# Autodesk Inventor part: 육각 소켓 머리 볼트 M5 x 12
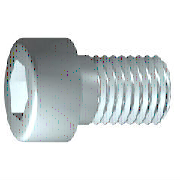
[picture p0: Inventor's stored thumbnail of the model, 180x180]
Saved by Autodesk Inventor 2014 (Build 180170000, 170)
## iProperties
Created: 2012-02
Part Number: 육각 소켓 머리 볼트 M5 x 12
Material: 강철, 연강
Description: 6각 소켓 머리 캡 나사
Document SubType Name: Modeling
Standard: ISO 4762
Designer: mdu-01
Standard Revision: Fourth edition 2004-03-01
Standards Organization: ISO
Language: ko-KR
Size Designation: M5 x 12
Categories: <MemberInstance><Categories><Category DisplayName="조임쇠" InternalName="e4da775c-781d-43d5-af7c-5136215cf5a6" Mnemonic="FSTN"><Category DisplayName="볼트" InternalN
Density: 7.86 g/cm^3
Appearance: 강철
Mass: 3.72825 g
Surface Area: 4.62573 cm^2
Volume: 0.474332 cm^3
Author: mdu-01
IsCustomPart: 1
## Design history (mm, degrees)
sketch "스케치1"
  geometry: L1 (-1.167, 0)-(12, 0); L2 (12, 0)-(12, 2.5); L3 (12, 2.5)-(2, 2.5); L4 (2, 2.5)-(1.509, 2.5); L5 (1.509, 2.5)-(0, 2.5); L6 (0, 2.5)-(0, 4.25); L7 (0, 4.25)-(-5, 4.25); L8 (-5, 4.25)-(-5, 2.309); L9 (-5, 2.309)-(-2.5, 2.309); L10 (-2.5, 2.309)-(-1.167, 0); L11 (-8.4, 0)-(15.4, 0) reference; L12 (0, -0.85)-(0, 5.1) reference; L13 (2, 2.5)-(0, 2.5)
  constraints: 22 end point, 6 parallel, 2 collinear, 2 perpendicular, 1 horizontal, 1 point on line
  dimensions: "d1" = 10 distance from line of L3.end L2 (= GEL); "d2" = 0.49086 distance of L4.end L3.end (computed from GAL); "d3" = 5 distance between parallel lines of L8 L6 (= KOH); "d4" = 2.5 distance of L8.end L9.end (= INTI); "d5" = 60 deg angle of L10 L1; "d6" = 5 diameter of L3 L1 (= GD); "d7" = 5 diameter of L5 L1 (= BDM); "d8" = 4.6188 diameter of L9 L1 (= 1.1547 x SW); "d9" = 8.5 diameter of L7 L1 (= KOD); "d26" = 12 distance between parallel lines of L12 L2 (= NLG)
revolve "본체" sketch "스케치1" stored, may be unused: angle "d10" = 90 deg
sketch "스케치2"
  geometry: L1 (0, -5.95)-(0, 5.95) reference; L2 (-5.95, 0)-(5.95, 0) reference; L3 (2.309, 0)-(1.155, -2); L4 (1.155, -2)-(-1.155, -2); L5 (-1.155, -2)-(-2.309, 0); L6 (-2.309, 0)-(-1.155, 2); L7 (-1.155, 2)-(1.155, 2); L8 (1.155, 2)-(2.309, 0); 2 further points
  constraints: 12 end point, 1 coincident, 1 horizontal alignment, 1 point on line, 12 other
extrude "슬롯" join sketch "스케치2" stored distance "d11" = 10; taper "d12" = 0 deg
workplane "Work Plane1"
fillet "Fillet2" dims "d30" = 0.1 (= R)
body "Solid1"
fillet "모깎기1" dims "d17" = 0.5 (= RR)
feature "스레드" dims "d13" = 10 (= GEL), "d14" = 0
chamfer "모따기1" distance "d15" = 0.49076 (= -0.5 x SPD + 0.5 x GD); stored, may be unused: second distance "d16" = 0.49076 (= GUL), angle "d27" = 45 deg
other parameters: "GD" = 5 [user parameter; used in 2 equation terms], "NLG" = 12 [user parameter; used in 1 equation term], "GEL" = 10 [user parameter; used in 2 equation terms], "KOD" = 8.5 [user parameter; used in 1 equation term], "KOH" = 5 [user parameter; used in 1 equation term], "INTI" = 2.5 [user parameter; used in 1 equation term], "GAL" = 0.49076 (= 0.61345 x PTC) [user parameter; used in 1 equation term], "GUL" = 0.49076 (= 0.61345 x PTC) [user parameter; used in 1 equation term], "BDM" = 5 (= NND) [user parameter; used in 1 equation term], "SW" = 4 [user parameter; used in 2 equation terms], "RR" = 0.5 [user parameter; used in 1 equation term], "SPD" = 4.01848 (= NND - 1.2269 x PTC) [user parameter; used in 1 equation term], "d19" = 0, "d28" = 0, "d29" = 0, "R" = 0.1 [user parameter; used in 1 equation term], "TOA" = 30 deg [user parameter], "GD1" = 4.01848 (= THREADDIA - 1.2269 x PTC) [user parameter], "THREADDIA" = 5 [user parameter; used in 1 equation term], "FAWI" = 45 deg [user parameter], "TPU" = 12.5 (computed from PTC) [user parameter], "PTC" = 0.8 [user parameter; used in 5 equation terms], "NND" = 5 [user parameter; used in 2 equation terms], "E0" = 4.62 (= 1.155 x SW) [user parameter]
